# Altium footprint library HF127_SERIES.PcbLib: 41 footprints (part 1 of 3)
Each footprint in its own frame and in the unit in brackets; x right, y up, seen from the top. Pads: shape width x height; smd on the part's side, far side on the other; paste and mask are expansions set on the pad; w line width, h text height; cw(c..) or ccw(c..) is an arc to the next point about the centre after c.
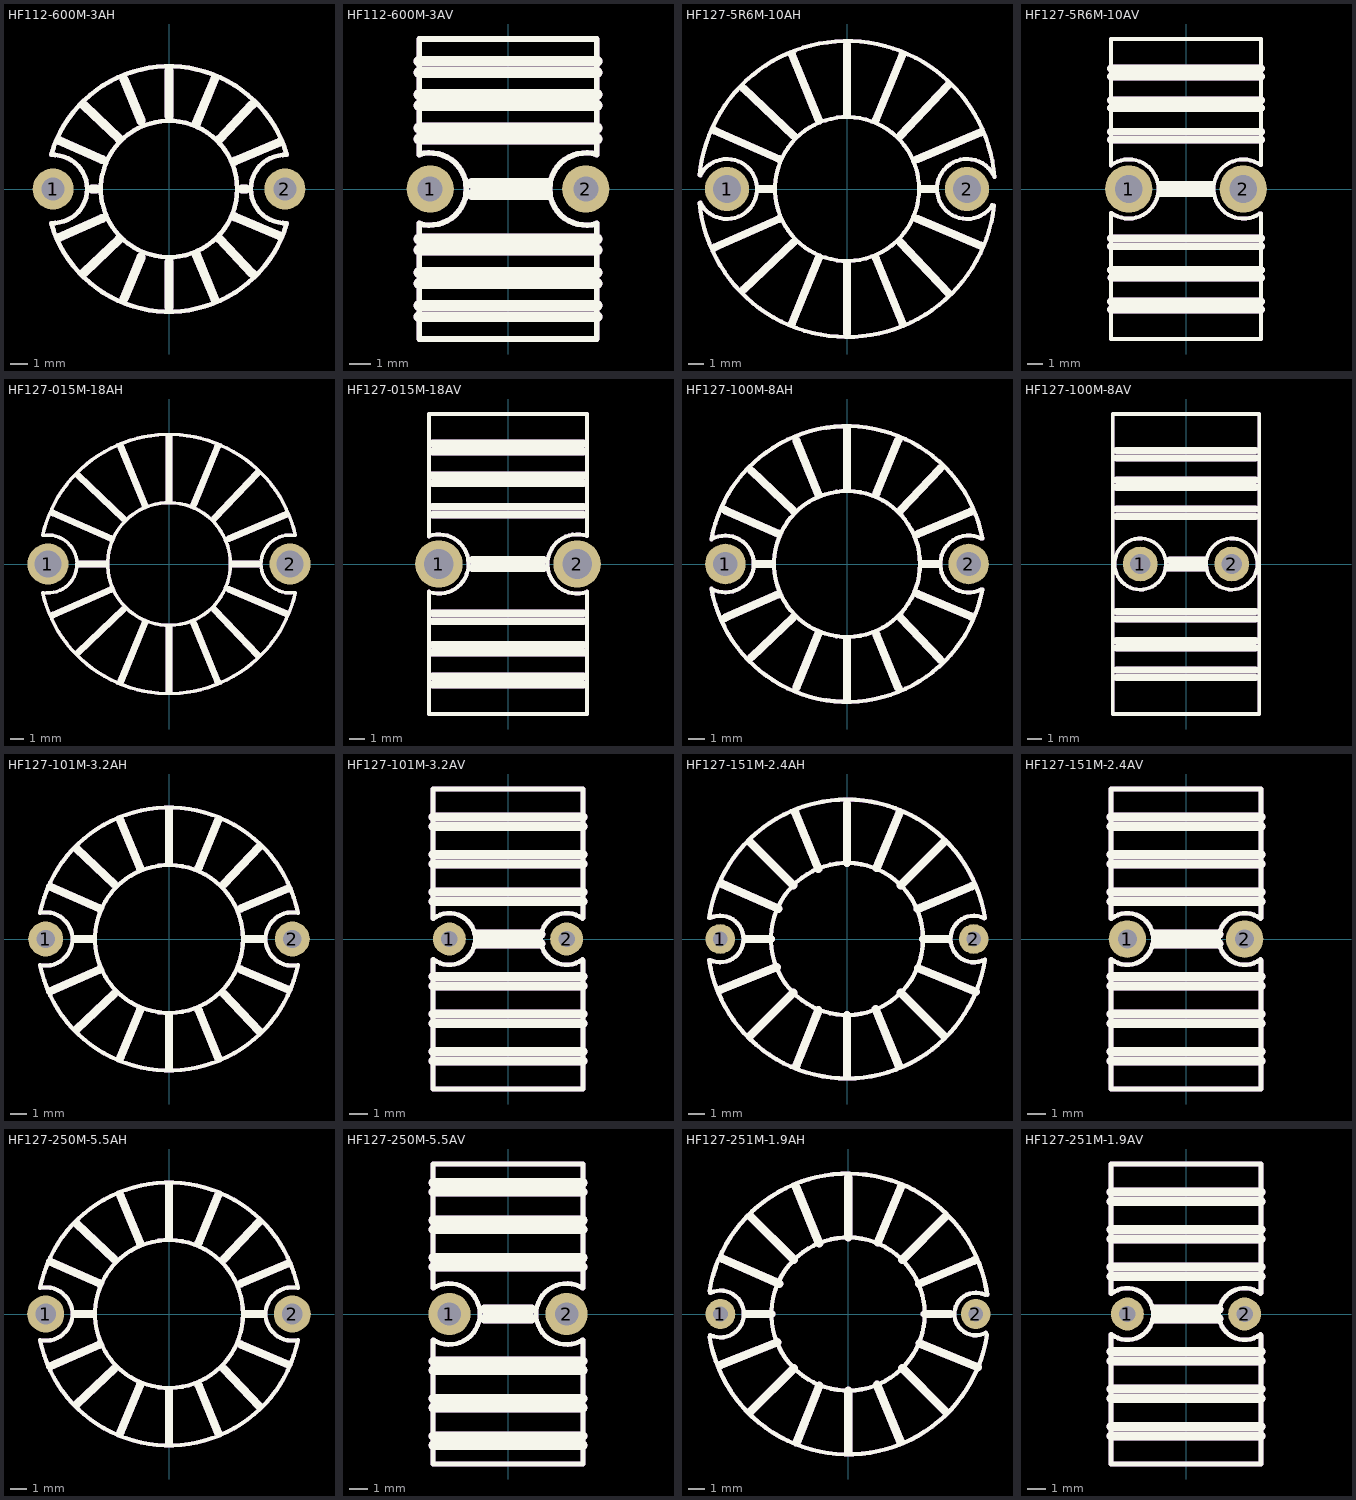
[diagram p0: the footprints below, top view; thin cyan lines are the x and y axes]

## HF112-600M-3AH [mil]
pads (2):
  round 90 hole 50: 1(-255,0) 2(255,0)
Top Overlay:
  circle w10: c0,0 r150
  lines w10: -259.39,-74.95 ccw(c0,0) 259.41,-74.87 cw(c255,0) 259.41,74.87 ccw(c0,0) -259.41,74.87 cw(c-255,0) -259.16,-74.88
  lines w19.68: -241.56,-106.45 -147.75,-65.11 ; -241.56,106.45 -147.75,65.11 ; -186.61,-183.58 -109.55,-110.47 ; -186.61,183.58 -109.55,110.47 ; -170,0 -160,0 ; -98.6,-240.58 -61.26,-149.48 ; -98.6,240.58 -61.26,149.48 ; 0,-260 0,-160 ; 0,160 0,260 ; 60.17,-144.03 101.02,-243.68 ; 60.17,144.03 101.02,243.68 ; 110.37,-109.11 183.37,-186.27 ; 110.37,109.11 183.37,186.27 ; 145.13,-61.5 244.28,-103.51 ; 145.13,61.5 244.28,103.51 ; 160,0 170,0
Mechanical 29:
  circle w10: c0,0 r150
  lines w10: -259.39,-74.95 ccw(c0,0) 259.41,-74.87 cw(c255,0) 259.41,74.87 ccw(c0,0) -259.41,74.87 cw(c-255,0) -259.16,-74.88
  lines w19.68: -241.56,-106.45 -147.75,-65.11 ; -241.56,106.45 -147.75,65.11 ; -186.61,-183.58 -109.55,-110.47 ; -186.61,183.58 -109.55,110.47 ; -170,0 -160,0 ; -98.6,-240.58 -61.26,-149.48 ; -98.6,240.58 -61.26,149.48 ; 0,-260 0,-160 ; 0,160 0,260 ; 60.17,-144.03 101.02,-243.68 ; 60.17,144.03 101.02,243.68 ; 110.37,-109.11 183.37,-186.27 ; 110.37,109.11 183.37,186.27 ; 145.13,-61.5 244.28,-103.51 ; 145.13,61.5 244.28,103.51 ; 160,0 170,0
  text "'.Designator'" at -1750,-64.85 h400

## HF112-600M-3AV [mil]
pads (2):
  round 85 hole 45: 1(-140,0) 2(140,0)
Top Overlay:
  lines w10: -160,-270 160,-270 160,-140 160,-61.85 cw(c140,0) 160,61.85 160,180 160,270 -160,270 -160,255 -160,61.85 cw(c-140,0) -160,-61.85 -160,-270
  lines w19.68: -160,-230 160,-230 ; -160,-210 160,-210 ; -160,-170 160,-170 ; -160,-150 160,-150 ; -160,-110 160,-110 ; -160,-90 160,-90 ; -160,90 160,90 ; -160,110 160,110 ; -160,150 160,150 ; -160,170 160,170 ; -160,210 160,210 ; -160,230 160,230 ; -65,-10 70,-10 ; -65,10 70,10
Mechanical 29:
  lines w10: -160,-270 160,-270 160,-140 160,-61.85 cw(c140,0) 160,61.85 160,180 160,270 -160,270 -160,255 -160,61.85 cw(c-140,0) -160,-61.85 -160,-270
  lines w19.68: -160,-230 160,-230 ; -160,-210 160,-210 ; -160,-170 160,-170 ; -160,-150 160,-150 ; -160,-110 160,-110 ; -160,-90 160,-90 ; -160,90 160,90 ; -160,110 160,110 ; -160,150 160,150 ; -160,170 160,170 ; -160,210 160,210 ; -160,230 160,230 ; -65,-10 70,-10 ; -65,10 70,10
  text "'.Designator'" at -1750,-64.85 h400

## HF127-5R6M-10AH [mil]
pads (2):
  round 110 hole 70: 1(-300,0) 2(300,0)
Top Overlay:
  circle w10: c0,0 r180
  lines w10: -368.36,-34.84 ccw(c0,0) 367.71,-41.07 ; -368.36,34.84 cw(c0,0) 368.79,29.88 ; -366.82,-34.06 ccw(c-300,0) -366.82,34.06 ; 363.09,-40.56 cw(c300,0) 368.94,29.54
  lines w19.68: -331.69,-146.17 -170.03,-74.93 ; -331.69,146.17 -170.03,74.93 ; -258.4,-251.69 -132.7,-132.43 ; -258.4,251.69 -132.7,132.43 ; -220,0 -185,0 ; -137.68,-335.95 -70.44,-171.87 ; -137.68,335.95 -70.44,171.87 ; 0,-360 0,-185 ; 0,185 0,360 ; 72.46,-173.99 138.67,-335.55 ; 72.46,173.99 138.67,335.55 ; 132.5,-132.5 254,-260.94 ; 132.5,132.5 254,260.94 ; 175.3,-74.28 334.3,-141.65 ; 175.3,74.28 334.3,141.65 ; 185,0 220,0
Mechanical 29:
  circle w10: c0,0 r180
  lines w10: -368.36,-34.84 ccw(c0,0) 367.71,-41.07 ; -368.36,34.84 cw(c0,0) 368.79,29.88 ; -366.82,-34.06 ccw(c-300,0) -366.82,34.06 ; 363.09,-40.56 cw(c300,0) 368.94,29.54
  lines w19.68: -331.69,-146.17 -170.03,-74.93 ; -331.69,146.17 -170.03,74.93 ; -258.4,-251.69 -132.7,-132.43 ; -258.4,251.69 -132.7,132.43 ; -220,0 -185,0 ; -137.68,-335.95 -70.44,-171.87 ; -137.68,335.95 -70.44,171.87 ; 0,-360 0,-185 ; 0,185 0,360 ; 72.46,-173.99 138.67,-335.55 ; 72.46,173.99 138.67,335.55 ; 132.5,-132.5 254,-260.94 ; 132.5,132.5 254,260.94 ; 175.3,-74.28 334.3,-141.65 ; 175.3,74.28 334.3,141.65 ; 185,0 220,0
  text "'.Designator'" at -1750,-64.85 h400

## HF127-5R6M-10AV [mil]
pads (2):
  round 120 hole 70: 1(-145,0) 2(145,0)
Top Overlay:
  lines w10: -190,-60.66 -190,-380 -90,-380 -30,-380 30,-380 70,-380 190,-380 190,-62.4 ; -189.11,-60.66 ccw(c-145,0) -190,60 -190,305 -190,380 189,380 ; 186.6,-62.4 cw(c145,0) 189.11,60.66 ; 190,60.66 190,380
  lines w19.68: -190,-305 190,-305 ; -190,-285 190,-285 ; -190,-205 190,-205 ; -190,-145 190,-145 ; -190,-125 190,-125 ; -190,125 190,125 ; -190,145 190,145 ; -190,205 190,205 ; -190,225 190,225 ; -190,285 190,285 ; -190,305 190,305 ; -189,-225 190,-225 ; -65,-10 65,-10 ; -65,10 65,10
Mechanical 29:
  lines w10: -190,-60.66 -190,-380 -90,-380 -30,-380 30,-380 70,-380 190,-380 190,-62.4 ; -189.11,-60.66 ccw(c-145,0) -190,60 -190,305 -190,380 189,380 ; 186.6,-62.4 cw(c145,0) 189.11,60.66 ; 190,60.66 190,380
  lines w19.68: -190,-305 190,-305 ; -190,-285 190,-285 ; -190,-205 190,-205 ; -190,-145 190,-145 ; -190,-125 190,-125 ; -190,125 190,125 ; -190,145 190,145 ; -190,205 190,205 ; -190,225 190,225 ; -190,285 190,285 ; -190,305 190,305 ; -189,-225 190,-225 ; -65,-10 65,-10 ; -65,10 65,10
  text "'.Designator'" at -1750,-64.85 h400

## HF127-015M-18AH [mil]
pads (2):
  round 120 hole 80: 1(-355,0) 2(355,0)
Top Overlay:
  circle w10: c0,0 r180
  lines w10: -370.7,-83.54 ccw(c0,0) 370.7,-83.54 cw(c355,0) 370.7,83.54 ccw(c0,0) -370.7,83.54 cw(c-355,0) -368.26,-83.96
  lines w19.68: -340.06,-149.86 -170.03,-74.93 ; -340.06,149.86 -170.03,74.93 ; -266.02,-258.92 -132.7,-132.43 ; -266.02,258.92 -132.7,132.43 ; -265,0 -185,0 ; -141.19,-344.51 -70.44,-171.87 ; -141.19,344.51 -70.44,171.87 ; 0,-375 0,-185 ; 0,185 0,375 ; 72.46,-173.99 142.18,-344.11 ; 72.46,173.99 142.18,344.11 ; 132.5,-132.5 261.36,-268.72 ; 132.5,132.5 261.36,268.72 ; 175.3,-74.28 344.57,-146.01 ; 175.3,74.28 344.57,146.01 ; 185,0 260,0
Mechanical 29:
  circle w10: c0,0 r180
  lines w10: -370.7,-83.54 ccw(c0,0) 370.7,-83.54 cw(c355,0) 370.7,83.54 ccw(c0,0) -370.7,83.54 cw(c-355,0) -368.26,-83.96
  lines w19.68: -340.06,-149.86 -170.03,-74.93 ; -340.06,149.86 -170.03,74.93 ; -266.02,-258.92 -132.7,-132.43 ; -266.02,258.92 -132.7,132.43 ; -265,0 -185,0 ; -141.19,-344.51 -70.44,-171.87 ; -141.19,344.51 -70.44,171.87 ; 0,-375 0,-185 ; 0,185 0,375 ; 72.46,-173.99 142.18,-344.11 ; 72.46,173.99 142.18,344.11 ; 132.5,-132.5 261.36,-268.72 ; 132.5,132.5 261.36,268.72 ; 175.3,-74.28 344.57,-146.01 ; 175.3,74.28 344.57,146.01 ; 185,0 260,0
  text "'.Designator'" at -1750,-64.85 h400

## HF127-015M-18AV [mil]
pads (2):
  round 120 hole 75: 1(-175,0) 2(175,0)
Top Overlay:
  lines w10: -200.23,70.63 cw(c-175,0) -197.37,-71.59 ; -200,-70 -200,-380 -90,-380 -30,-380 30,-380 70,-380 200,-380 200,-70 ; -200,70 -200,295 -200,380 200,380 200,220 200,75 ; 198.72,-71.15 cw(c175,0) 200.23,70.63
  lines w19.68: -195,-225 195,-225 ; -195,225 195,225 ; -190,-305 190,-305 ; -190,-285 190,-285 ; -190,-205 190,-205 ; -190,-145 190,-145 ; -190,-125 190,-125 ; -190,125 190,125 ; -190,145 190,145 ; -190,205 190,205 ; -190,285 190,285 ; -190,305 190,305 ; -90,-10 90,-10 ; -90,10 90,10
Mechanical 29:
  lines w10: -200.23,70.63 cw(c-175,0) -197.37,-71.59 ; -200,-70 -200,-380 -90,-380 -30,-380 30,-380 70,-380 200,-380 200,-70 ; -200,70 -200,295 -200,380 200,380 200,220 200,75 ; 198.72,-71.15 cw(c175,0) 200.23,70.63
  lines w19.68: -195,-225 195,-225 ; -195,225 195,225 ; -190,-305 190,-305 ; -190,-285 190,-285 ; -190,-205 190,-205 ; -190,-145 190,-145 ; -190,-125 190,-125 ; -190,125 190,125 ; -190,145 190,145 ; -190,205 190,205 ; -190,285 190,285 ; -190,305 190,305 ; -90,-10 90,-10 ; -90,10 90,10
  text "'.Designator'" at -1750,-64.85 h400

## HF127-100M-8AH [mil]
pads (2):
  round 100 hole 60: 1(-300,0) 2(300,0)
Top Overlay:
  circle w10: c0,0 r180
  lines w10: 330.9,-62.81 cw(c300,0) 330.9,62.81 ; 334.04,-63.4 cw(c0,0) -334.5,-60.91 ccw(c-300,0) -334.5,60.91 cw(c0,0) 334.04,63.4
  lines w19.68: -301.03,-132.66 -170.03,-74.93 ; -301.03,132.66 -170.03,74.93 ; -235.26,-229.73 -132.7,-132.43 ; -235.26,229.73 -132.7,132.43 ; -225,0 -185,0 ; -125,-305 -70.44,-171.87 ; -125,305 -70.44,171.87 ; 0,-335 0,-185 ; 0,185 0,335 ; 72.46,-173.99 126.7,-306.35 ; 72.46,173.99 126.7,306.35 ; 132.5,-132.5 229.71,-235.27 ; 132.5,132.5 229.71,235.27 ; 175.3,-74.28 305.27,-129.35 ; 175.3,74.28 305.27,129.35 ; 185,0 225,0
Mechanical 29:
  circle w10: c0,0 r180
  lines w10: 330.9,-62.81 cw(c300,0) 330.9,62.81 ; 334.04,-63.4 cw(c0,0) -334.5,-60.91 ccw(c-300,0) -334.5,60.91 cw(c0,0) 334.04,63.4
  lines w19.68: -301.03,-132.66 -170.03,-74.93 ; -301.03,132.66 -170.03,74.93 ; -235.26,-229.73 -132.7,-132.43 ; -235.26,229.73 -132.7,132.43 ; -225,0 -185,0 ; -125,-305 -70.44,-171.87 ; -125,305 -70.44,171.87 ; 0,-335 0,-185 ; 0,185 0,335 ; 72.46,-173.99 126.7,-306.35 ; 72.46,173.99 126.7,306.35 ; 132.5,-132.5 229.71,-235.27 ; 132.5,132.5 229.71,235.27 ; 175.3,-74.28 305.27,-129.35 ; 175.3,74.28 305.27,129.35 ; 185,0 225,0
  text "'.Designator'" at -1750,-64.85 h400

## HF127-100M-8AV [mil]
pads (2):
  round 95 hole 55: 1(-125,0) 2(125,0)
Top Overlay:
  lines w10: -195,0 ccw(c-125,0) -194.82,4.99 ; 194.82,4.99 ccw(c125,0) 195,0 ; 200,-57.45 200,-410 -200,-410 -200,-60 -200,410 200,410 200,-55
  lines w19.68: -190,-310 190,-310 ; -190,-290 190,-290 ; -190,-230 190,-230 ; -190,-210 190,-210 ; -190,-150 190,-150 ; -190,-130 190,-130 ; -190,130 190,130 ; -190,150 190,150 ; -190,210 190,210 ; -190,230 190,230 ; -190,290 190,290 ; -190,310 190,310 ; -50,-10 50,-10 ; -45,10 50,10
Mechanical 29:
  lines w10: -195,0 ccw(c-125,0) -194.82,4.99 ; 194.82,4.99 ccw(c125,0) 195,0 ; 200,-57.45 200,-410 -200,-410 -200,-60 -200,410 200,410 200,-55
  lines w19.68: -190,-310 190,-310 ; -190,-290 190,-290 ; -190,-230 190,-230 ; -190,-210 190,-210 ; -190,-150 190,-150 ; -190,-130 190,-130 ; -190,130 190,130 ; -190,150 190,150 ; -190,210 190,210 ; -190,230 190,230 ; -190,290 190,290 ; -190,310 190,310 ; -50,-10 50,-10 ; -45,10 50,10
  text "'.Designator'" at -1750,-64.85 h400

## HF127-101M-3.2AH [mil]
pads (2):
  round 85 hole 45: 1(-300,0) 2(300,0)
Top Overlay:
  circle w10: c0,0 r180
  lines w10: -313.62,-63.56 ccw(c0,0) 313.62,-63.56 cw(c300,0) 313.62,63.56 ccw(c0,0) -313.62,63.56 cw(c-300,0) -313.62,-63.56
  lines w19.68: -288.97,-127.34 -170.03,-74.93 ; -288.97,127.34 -170.03,74.93 ; -230,0 -185,0 ; -225,-220 -132.7,-132.43 ; -225,220 -132.7,132.43 ; -118.3,-288.65 -70.44,-171.87 ; -118.3,288.65 -70.44,171.87 ; 0,-315 0,-185 ; 0,185 0,315 ; 72.46,-173.99 120,-290 ; 72.46,173.99 120,290 ; 132.5,-132.5 220,-225 ; 132.5,132.5 220,225 ; 175.3,-74.28 290.76,-123.2 ; 175.3,74.28 290.76,123.2 ; 185,0 230,0
Mechanical 29:
  circle w10: c0,0 r180
  lines w10: -313.62,-63.56 ccw(c0,0) 313.62,-63.56 cw(c300,0) 313.62,63.56 ccw(c0,0) -313.62,63.56 cw(c-300,0) -313.62,-63.56
  lines w19.68: -288.97,-127.34 -170.03,-74.93 ; -288.97,127.34 -170.03,74.93 ; -230,0 -185,0 ; -225,-220 -132.7,-132.43 ; -225,220 -132.7,132.43 ; -118.3,-288.65 -70.44,-171.87 ; -118.3,288.65 -70.44,171.87 ; 0,-315 0,-185 ; 0,185 0,315 ; 72.46,-173.99 120,-290 ; 72.46,173.99 120,290 ; 132.5,-132.5 220,-225 ; 132.5,132.5 220,225 ; 175.3,-74.28 290.76,-123.2 ; 175.3,74.28 290.76,123.2 ; 185,0 230,0
  text "'.Designator'" at -1750,-64.85 h400

## HF127-101M-3.2AV [mil]
pads (2):
  round 70 hole 35: 1(-125,0) 2(125,0)
Top Overlay:
  lines w10: -160,-43.44 -160,-320 -90,-320 -30,-320 30,-320 70,-320 160,-320 160,-140 160,-45 ; -160,43.44 -160,255 -160,320 160,320 160,180 160,45 ; -158.74,-43.44 ccw(c-125,0) -158.74,43.44 ; 158.77,-43.41 cw(c125,0) 158.77,43.41
  lines w19.68: -160,-260 160,-260 ; -160,-240 160,-240 ; -160,-180 160,-180 ; -160,-160 160,-160 ; -160,-100 160,-100 ; -160,-80 160,-80 ; -160,80 160,80 ; -160,100 160,100 ; -160,160 160,160 ; -160,180 160,180 ; -160,240 160,240 ; -160,260 160,260 ; -65,-10 70,-10 ; -65,10 70,10
Mechanical 29:
  lines w10: -160,-43.44 -160,-320 -90,-320 -30,-320 30,-320 70,-320 160,-320 160,-140 160,-45 ; -160,43.44 -160,255 -160,320 160,320 160,180 160,45 ; -158.74,-43.44 ccw(c-125,0) -158.74,43.44 ; 158.77,-43.41 cw(c125,0) 158.77,43.41
  lines w19.68: -160,-260 160,-260 ; -160,-240 160,-240 ; -160,-180 160,-180 ; -160,-160 160,-160 ; -160,-100 160,-100 ; -160,-80 160,-80 ; -160,80 160,80 ; -160,100 160,100 ; -160,160 160,160 ; -160,180 160,180 ; -160,240 160,240 ; -160,260 160,260 ; -65,-10 70,-10 ; -65,10 70,10
  text "'.Designator'" at -1750,-64.85 h400

## HF127-151M-2.4AH  [mil]
pads (2):
  round 70 hole 35: 1(-300,0) 2(300,0)
Top Overlay:
  circle w10: c0,0 r180
  lines w10: -326.19,-49.98 ccw(c0,0) 326.34,-49.02 ; -326.19,50.02 cw(c0,0) 326.27,49.45 ; -323.75,-49.61 ccw(c-300,0) -323.69,49.64 ; 324.6,49.19 ccw(c300,0) 326.03,-48.45
  lines w19.68: -300,-120 -166.38,-66.55 ; -295,130 -162.15,71.46 ; -240,0 -180,0 ; -230,-230 -127.5,-127.5 ; -230,230 -127.5,127.5 ; -122.53,298.96 -67.96,165.83 ; -120,-300 -67.59,-168.97 ; 0,-325 0,-180 ; 0,180 0,320 ; 67.96,-165.83 123.25,-300.72 ; 69.97,167.93 125,300 ; 127.5,-127.5 227.5,-227.5 ; 127.5,127.5 230,230 ; 167.47,70.96 295,125 ; 168.36,-69 305,-125 ; 180,0 240,0
Mechanical 29:
  circle w10: c0,0 r180
  lines w10: -326.19,-49.98 ccw(c0,0) 326.34,-49.02 ; -325.61,53.66 cw(c0,0) 326.27,49.45 ; -323.75,-49.61 ccw(c-300,0) -323.69,49.64 ; 324.6,49.19 ccw(c300,0) 326.03,-48.45
  lines w19.68: -300,-120 -166.38,-66.55 ; -295,130 -162.15,71.46 ; -240,0 -180,0 ; -230,-230 -127.5,-127.5 ; -230,230 -127.5,127.5 ; -122.53,298.96 -67.96,165.83 ; -120,-300 -67.59,-168.97 ; 0,-325 0,-180 ; 0,180 0,320 ; 67.96,-165.83 123.25,-300.72 ; 69.97,167.93 125,300 ; 127.5,-127.5 227.5,-227.5 ; 127.5,127.5 230,230 ; 167.47,70.96 295,125 ; 168.36,-69 305,-125 ; 180,0 240,0
  text "'.Designator'" at -1400,-124.85 h400

## HF127-151M-2.4AV [mil]
pads (2):
  round 80 hole 40: 1(-125,0) 2(125,0)
Top Overlay:
  lines w10: -160,-43.44 -160,-320 -90,-320 -30,-320 30,-320 70,-320 160,-320 160,-140 160,-45 ; -160,43.44 -160,255 -160,320 160,320 160,180 160,45 ; -158.74,-43.44 ccw(c-125,0) -158.74,43.44 ; 158.77,-43.41 cw(c125,0) 158.77,43.41
  lines w19.68: -160,-260 160,-260 ; -160,-240 160,-240 ; -160,-180 160,-180 ; -160,-160 160,-160 ; -160,-100 160,-100 ; -160,-80 160,-80 ; -160,80 160,80 ; -160,100 160,100 ; -160,160 160,160 ; -160,180 160,180 ; -160,240 160,240 ; -160,260 160,260 ; -65,-10 70,-10 ; -65,10 70,10
Mechanical 29:
  lines w10: -160,-43.44 -160,-320 -90,-320 -30,-320 30,-320 70,-320 160,-320 160,-140 160,-45 ; -160,43.44 -160,255 -160,320 160,320 160,180 160,45 ; -158.74,-43.44 ccw(c-125,0) -158.74,43.44 ; 158.77,-43.41 cw(c125,0) 158.77,43.41
  lines w19.68: -160,-260 160,-260 ; -160,-240 160,-240 ; -160,-180 160,-180 ; -160,-160 160,-160 ; -160,-100 160,-100 ; -160,-80 160,-80 ; -160,80 160,80 ; -160,100 160,100 ; -160,160 160,160 ; -160,180 160,180 ; -160,240 160,240 ; -160,260 160,260 ; -65,-10 70,-10 ; -65,10 70,10
  text "'.Designator'" at -1750,-64.85 h400

## HF127-250M-5.5AH [mil]
pads (2):
  round 90 hole 50: 1(-300,0) 2(300,0)
Top Overlay:
  circle w10: c0,0 r180
  lines w10: -313.62,-63.56 ccw(c-300,0) -313.62,63.56 cw(c0,0) 313.62,63.56 ccw(c300,0) 313.62,-63.56 cw(c0,0) -313.62,-63.56
  lines w19.68: -288.97,-127.34 -170.03,-74.93 ; -288.97,127.34 -170.03,74.93 ; -230,0 -185,0 ; -225,-220 -132.7,-132.43 ; -225,220 -132.7,132.43 ; -118.3,-288.65 -70.44,-171.87 ; -118.3,288.65 -70.44,171.87 ; 0,-315 0,-185 ; 0,185 0,315 ; 72.46,-173.99 120,-290 ; 72.46,173.99 120,290 ; 132.5,-132.5 220,-225 ; 132.5,132.5 220,225 ; 175.3,-74.28 290.76,-123.2 ; 175.3,74.28 290.76,123.2 ; 185,0 230,0
Mechanical 29:
  circle w10: c0,0 r180
  lines w10: -313.62,-63.56 ccw(c-300,0) -313.62,63.56 cw(c0,0) 313.62,63.56 ccw(c300,0) 313.62,-63.56 cw(c0,0) -313.62,-63.56
  lines w19.68: -288.97,-127.34 -170.03,-74.93 ; -288.97,127.34 -170.03,74.93 ; -230,0 -185,0 ; -225,-220 -132.7,-132.43 ; -225,220 -132.7,132.43 ; -118.3,-288.65 -70.44,-171.87 ; -118.3,288.65 -70.44,171.87 ; 0,-315 0,-185 ; 0,185 0,315 ; 72.46,-173.99 120,-290 ; 72.46,173.99 120,290 ; 132.5,-132.5 220,-225 ; 132.5,132.5 220,225 ; 175.3,-74.28 290.76,-123.2 ; 175.3,74.28 290.76,123.2 ; 185,0 230,0
  text "'.Designator'" at -1750,-64.85 h400

## HF127-250M-5.5AV [mil]
pads (2):
  round 90 hole 50: 1(-125,0) 2(125,0)
Top Overlay:
  lines w10: -160,-320 -90,-320 -30,-320 30,-320 70,-320 160,-320 160,-140 160,-54.77 cw(c125,0) 160,54.77 160,180 160,320 -160,320 -160,255 -160,54.77 cw(c-125,0) -160,-54.77 -160,-320
  lines w19.68: -160,-280 160,-280 ; -160,-260 160,-260 ; -160,-200 160,-200 ; -160,-180 160,-180 ; -160,-120 160,-120 ; -160,-100 160,-100 ; -160,100 160,100 ; -160,120 160,120 ; -160,180 160,180 ; -160,200 160,200 ; -160,260 160,260 ; -160,280 160,280 ; -50,-10 50,-10 ; -50,10 50,10
Mechanical 29:
  lines w10: -160,-320 -90,-320 -30,-320 30,-320 70,-320 160,-320 160,-140 160,-54.77 cw(c125,0) 160,54.77 160,180 160,320 -160,320 -160,255 -160,54.77 cw(c-125,0) -160,-54.77 -160,-320
  lines w19.68: -160,-280 160,-280 ; -160,-260 160,-260 ; -160,-200 160,-200 ; -160,-180 160,-180 ; -160,-120 160,-120 ; -160,-100 160,-100 ; -160,100 160,100 ; -160,120 160,120 ; -160,180 160,180 ; -160,200 160,200 ; -160,260 160,260 ; -160,280 160,280 ; -50,-10 50,-10 ; -50,10 50,10
  text "'.Designator'" at -1750,-64.85 h400

## HF127-251M-1.9AH  [mil]
pads (2):
  round 70 hole 35: 1(-300,0) 2(300,0)
Top Overlay:
  circle w10: c0,0 r180
  lines w10: -325.63,-53.53 ccw(c0,0) 326.34,-49.02 ; -325.61,53.66 cw(c0,0) 326.87,45.35 ; -323.75,-49.61 ccw(c-300,0) -323.69,49.64 ; 322.36,44.72 ccw(c300,0) 323.67,-44.04
  lines w19.68: -300,-120 -166.38,-66.55 ; -295,130 -162.15,71.46 ; -240,0 -180,0 ; -230,-230 -127.5,-127.5 ; -230,230 -127.5,127.5 ; -122.53,298.96 -67.96,165.83 ; -120,-300 -67.59,-168.97 ; 0,-325 0,-180 ; 0,180 0,320 ; 67.96,-165.83 123.25,-300.72 ; 69.97,167.93 125,300 ; 127.5,-127.5 227.5,-227.5 ; 127.5,127.5 230,230 ; 167.47,70.96 295,125 ; 168.36,-69 305,-125 ; 180,0 240,0
Mechanical 29:
  circle w10: c0,0 r180
  lines w10: -325.63,-53.53 ccw(c0,0) 326.34,-49.02 ; -325.61,53.66 cw(c0,0) 326.87,45.35 ; -323.75,-49.61 ccw(c-300,0) -323.69,49.64 ; 322.36,44.72 ccw(c300,0) 323.67,-44.04
  lines w19.68: -300,-120 -166.38,-66.55 ; -295,130 -162.15,71.46 ; -240,0 -180,0 ; -230,-230 -127.5,-127.5 ; -230,230 -127.5,127.5 ; -122.53,298.96 -67.96,165.83 ; -120,-300 -67.59,-168.97 ; 0,-325 0,-180 ; 0,180 0,320 ; 67.96,-165.83 123.25,-300.72 ; 69.97,167.93 125,300 ; 127.5,-127.5 227.5,-227.5 ; 127.5,127.5 230,230 ; 167.47,70.96 295,125 ; 168.36,-69 305,-125 ; 180,0 240,0
  text "'.Designator'" at -1750,-64.85 h400

## HF127-251M-1.9AV [mil]
pads (2):
  round 70 hole 35: 1(-125,0) 2(125,0)
Top Overlay:
  lines w10: -160,-43.44 -160,-320 -90,-320 -30,-320 30,-320 70,-320 160,-320 160,-140 160,-45 ; -160,43.44 -160,255 -160,320 160,320 160,180 160,45 ; -158.74,-43.44 ccw(c-125,0) -158.74,43.44 ; 158.77,-43.41 cw(c125,0) 158.77,43.41
  lines w19.68: -160,-260 160,-260 ; -160,-240 160,-240 ; -160,-180 160,-180 ; -160,-160 160,-160 ; -160,-100 160,-100 ; -160,-80 160,-80 ; -160,80 160,80 ; -160,100 160,100 ; -160,160 160,160 ; -160,180 160,180 ; -160,240 160,240 ; -160,260 160,260 ; -65,-10 70,-10 ; -65,10 70,10
Mechanical 29:
  lines w10: -160,-43.44 -160,-320 -90,-320 -30,-320 30,-320 70,-320 160,-320 160,-140 160,-45 ; -160,43.44 -160,255 -160,320 160,320 160,180 160,45 ; -158.74,-43.44 ccw(c-125,0) -158.74,43.44 ; 158.77,-43.41 cw(c125,0) 158.77,43.41
  lines w19.68: -160,-260 160,-260 ; -160,-240 160,-240 ; -160,-180 160,-180 ; -160,-160 160,-160 ; -160,-100 160,-100 ; -160,-80 160,-80 ; -160,80 160,80 ; -160,100 160,100 ; -160,160 160,160 ; -160,180 160,180 ; -160,240 160,240 ; -160,260 160,260 ; -65,-10 70,-10 ; -65,10 70,10
  text "'.Designator'" at -1750,-64.85 h400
